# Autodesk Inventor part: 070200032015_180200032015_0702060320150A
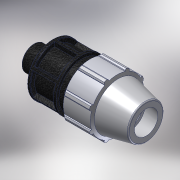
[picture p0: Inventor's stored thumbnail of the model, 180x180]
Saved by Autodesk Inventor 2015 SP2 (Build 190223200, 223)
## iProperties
Created: 2017-02
Part Number: 070200032015_180200032015_0702060320150A
Material: PVC-Piping
Description: PLASSON MALE ADAPTOR 32-1.1/2"
Document SubType Name: Modeling
Designer: KIM
Mass: 92.6774 g
Surface Area: 199.44 cm^2
Volume: 66.1981 cm^3
Density: 1.4 g/cm^3
Appearance: PTFE
Author: KIM
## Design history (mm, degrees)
derived "07020.ipt"
feature "Solid1::07020.ipt"
tag "TaggingFeature1"
body "Solid1"
other parameters: "d2" = 32, "d4" = 15.71429, "d5" = 27.5, "d7" = 64, "d8" = 48, "d9" = 15.71429, "d11" = 3.14286, "d12" = 51.2, "d13" = 120 deg, "d14" = 48, "d15" = 10 deg, "d16" = 57.6, "d18" = 1.6, "d19" = 35 deg, "d20" = 17.5 deg, "d21" = 59.52, "d23" = 0, "d25" = 360 deg, "d27" = 1.28, "d34" = 3.2, "d36" = 0, "d42" = 27.5, "d43" = 1.92, "d46" = 0.96, "d49" = 83, "d52" = 22, "d53" = 0.64, "d55" = 360 deg, "d57" = 47.803, "d58" = 28.6818, "d59" = 22, "d_" = 32, "E_" = 64, "l_" = 83, "l_2" = 22, "R_" = 47.803
